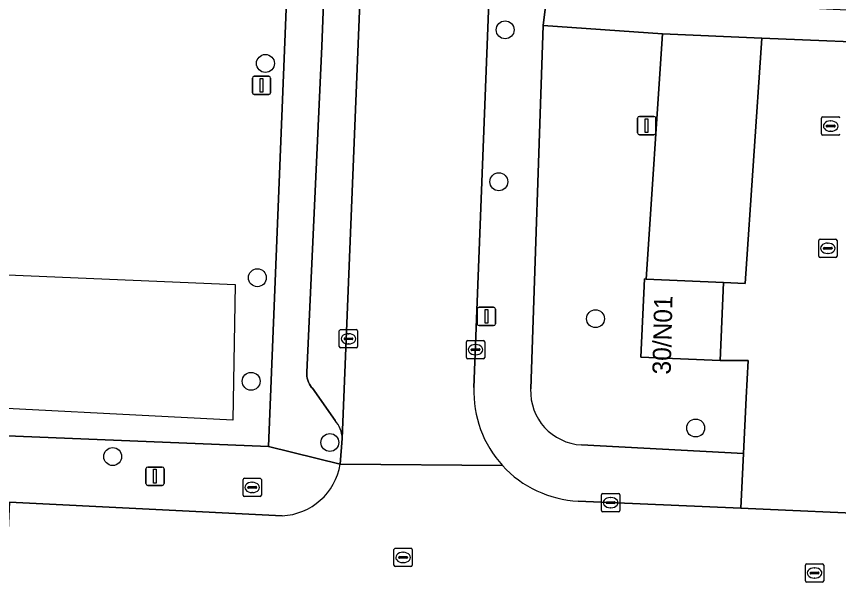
# Model space of a CAD drawing. Extents: x 161354 to 162026, y 386504 to 387460.
# Drawn here: x 161422.95 to 161467.8, y 386572.23 to 386603.95 of the extents above; entities that cross this region are included whole.
import ezdxf

# ---------------------------------------------------------------- set-up
doc = ezdxf.new("R2010")
doc.units = 0
for name, color, linetype in [('IMGEO_Boom', 7, 'Continuous'), ('IMGEO_Erf', 7, 'Continuous'), ('IMGEO_Groenvoorziening', 7, 'Continuous'), ('IMGEO_Kolk', 7, 'Continuous'), ('IMGEO_Lichtmast', 7, 'Continuous'), ('IMGEO_Pand', 7, 'Continuous'), ('IMGEO_Pand_nummerreeks', 7, 'Continuous'), ('IMGEO_Pand_vergunning_verleend', 7, 'Continuous'), ('IMGEO_Parkeervlak_open', 7, 'Continuous'), ('IMGEO_Rijbaan_lokaal_open', 7, 'Continuous'), ('IMGEO_Rioolput', 7, 'Continuous'), ('IMGEO_Voetpad_open', 7, 'Continuous')]:
    doc.layers.add(name, color=color, linetype=linetype)

msp = doc.modelspace()

# ---------------------------------------------------------------- linework, layer by layer
at = {"layer": 'IMGEO_Boom'}
for centre in [(161449.613, 386603.218), (161436.536, 386601.385), (161449.267, 386594.926), (161436.096, 386589.686), (161454.542, 386587.45), (161435.755, 386584.032), (161460.006, 386581.483), (161440.05, 386580.692), (161428.203, 386579.924)]:
    msp.add_circle(centre, 0.489, dxfattribs=at)
at = {"layer": 'IMGEO_Erf'}
msp.add_lwpolyline([(161420.217, 386581.152), (161436.711, 386580.469), (161438.937, 386635.916), (161439.242, 386644.412), (161439.468, 386649.379), (161441.486, 386649.282), (161445.22, 386736.534)], dxfattribs=at)
at = {"layer": 'IMGEO_Groenvoorziening'}
for points in [[(161458.197, 386602.999), (161451.688, 386603.457), (161451.005, 386583.617)], [(161453.783, 386580.56), (161462.617, 386580.096), (161462.764, 386583.132), (161462.863, 386585.172), (161461.34, 386585.162), (161457.019, 386585.355), (161457.209, 386589.618), (161457.314, 386589.613), (161458.197, 386602.999)]]:
    msp.add_lwpolyline(points, dxfattribs=at)
msp.add_arc((161453.937, 386583.491), 2.935, 177.5297, 266.9953, dxfattribs=at)
at = {"layer": 'IMGEO_Kolk'}
for p, q in [((161466.716, 386590.868), (161466.716, 386591.72)), ((161466.791, 386591.794), (161467.643, 386591.794)), ((161467.717, 386591.72), (161467.717, 386590.868)), ((161466.975, 386591.288), (161466.975, 386591.3)), ((161467.413, 386591.251), (161467.015, 386591.251)), ((161467.018, 386591.337), (161467.416, 386591.337)), ((161467.204, 386591.574), (161467.229, 386591.574)), ((161467.459, 386591.3), (161467.459, 386591.288)), ((161467.643, 386590.794), (161466.791, 386590.794)), ((161467.227, 386591.014), (161467.202, 386591.014)), ((161440.565, 386585.927), (161440.565, 386586.779)), ((161440.64, 386586.853), (161441.492, 386586.853)), ((161441.566, 386586.779), (161441.566, 386585.927)), ((161440.824, 386586.347), (161440.824, 386586.359)), ((161441.262, 386586.31), (161440.864, 386586.31)), ((161440.867, 386586.396), (161441.265, 386586.396)), ((161441.053, 386586.633), (161441.078, 386586.633)), ((161441.308, 386586.359), (161441.308, 386586.347)), ((161447.571, 386586.258), (161448.423, 386586.258)), ((161441.492, 386585.853), (161440.64, 386585.853)), ((161441.076, 386586.073), (161441.051, 386586.073)), ((161447.496, 386585.332), (161447.496, 386586.184)), ((161447.755, 386585.752), (161447.755, 386585.764)), ((161447.798, 386585.801), (161448.196, 386585.801)), ((161447.984, 386586.038), (161448.009, 386586.038)), ((161448.239, 386585.764), (161448.239, 386585.752)), ((161448.497, 386586.184), (161448.497, 386585.332)), ((161448.193, 386585.715), (161447.795, 386585.715)), ((161448.007, 386585.478), (161447.982, 386585.478)), ((161448.423, 386585.258), (161447.571, 386585.258)), ((161435.313, 386577.813), (161435.313, 386578.665)), ((161435.388, 386578.739), (161436.24, 386578.739)), ((161436.314, 386578.665), (161436.314, 386577.813)), ((161435.572, 386578.233), (161435.572, 386578.245)), ((161436.01, 386578.196), (161435.612, 386578.196)), ((161435.615, 386578.282), (161436.013, 386578.282)), ((161435.801, 386578.519), (161435.826, 386578.519)), ((161436.056, 386578.245), (161436.056, 386578.233)), ((161436.24, 386577.739), (161435.388, 386577.739)), ((161435.824, 386577.959), (161435.799, 386577.959)), ((161454.867, 386576.983), (161454.867, 386577.835)), ((161454.942, 386577.909), (161455.794, 386577.909)), ((161455.868, 386577.835), (161455.868, 386576.983)), ((161455.126, 386577.403), (161455.126, 386577.415)), ((161455.564, 386577.366), (161455.166, 386577.366)), ((161455.169, 386577.452), (161455.567, 386577.452)), ((161455.355, 386577.689), (161455.38, 386577.689)), ((161455.61, 386577.415), (161455.61, 386577.403)), ((161455.794, 386576.909), (161454.942, 386576.909)), ((161455.378, 386577.129), (161455.353, 386577.129))]:
    msp.add_line(p, q, dxfattribs=at)
for points in [[(161466.716, 386590.868), (161466.716, 386591.72)], [(161466.791, 386591.794), (161467.643, 386591.794)], [(161467.717, 386591.72), (161467.717, 386590.868)], [(161467.643, 386590.794), (161466.791, 386590.794)], [(161440.565, 386585.927), (161440.565, 386586.779)], [(161440.64, 386586.853), (161441.492, 386586.853)], [(161441.566, 386586.779), (161441.566, 386585.927)], [(161447.571, 386586.258), (161448.423, 386586.258)], [(161441.492, 386585.853), (161440.64, 386585.853)], [(161447.496, 386585.332), (161447.496, 386586.184)], [(161448.497, 386586.184), (161448.497, 386585.332)], [(161448.423, 386585.258), (161447.571, 386585.258)], [(161435.313, 386577.813), (161435.313, 386578.665)], [(161435.388, 386578.739), (161436.24, 386578.739)], [(161436.314, 386578.665), (161436.314, 386577.813)], [(161436.24, 386577.739), (161435.388, 386577.739)], [(161454.867, 386576.983), (161454.867, 386577.835)], [(161454.942, 386577.909), (161455.794, 386577.909)], [(161455.868, 386577.835), (161455.868, 386576.983)], [(161455.794, 386576.909), (161454.942, 386576.909)]]:
    msp.add_lwpolyline(points, dxfattribs=at)
for centre, radius, start, end in [((161466.793, 386591.718), 0.0765, 91.552, 178.448), ((161466.793, 386591.718), 0.0765, 91.552, 178.448), ((161467.641, 386591.718), 0.0765, 1.552, 88.448), ((161467.641, 386591.718), 0.0765, 1.552, 88.448), ((161467.015, 386591.297), 0.0403, 85.8775, 175.7526), ((161467.012, 386591.287), 0.0366, 178.938, 274.7102), ((161467.416, 386591.294), 0.043, 264.8664, 352.4533), ((161467.42, 386591.299), 0.0386, 1.7309, 96.639), ((161466.793, 386590.87), 0.0765, 181.552, 268.448), ((161466.793, 386590.87), 0.0765, 181.552, 268.448), ((161467.641, 386590.87), 0.0765, 271.552, 358.448), ((161467.641, 386590.87), 0.0765, 271.552, 358.448), ((161440.642, 386586.777), 0.0765, 91.552, 178.448), ((161440.642, 386586.777), 0.0765, 91.552, 178.448), ((161441.49, 386586.777), 0.0765, 1.552, 88.448), ((161441.49, 386586.777), 0.0765, 1.552, 88.448), ((161440.864, 386586.356), 0.0403, 85.8775, 175.7526), ((161440.861, 386586.346), 0.0366, 178.938, 274.7102), ((161441.265, 386586.353), 0.043, 264.8664, 352.4533), ((161441.269, 386586.358), 0.0386, 1.7309, 96.639), ((161447.573, 386586.182), 0.0765, 91.552, 178.448), ((161447.573, 386586.182), 0.0765, 91.552, 178.448), ((161448.421, 386586.182), 0.0765, 1.552, 88.448), ((161448.421, 386586.182), 0.0765, 1.552, 88.448), ((161440.642, 386585.929), 0.0765, 181.552, 268.448), ((161440.642, 386585.929), 0.0765, 181.552, 268.448), ((161441.49, 386585.929), 0.0765, 271.552, 358.448), ((161441.49, 386585.929), 0.0765, 271.552, 358.448), ((161447.795, 386585.761), 0.0403, 85.8775, 175.7526), ((161448.2, 386585.763), 0.0386, 1.7309, 96.639), ((161447.573, 386585.334), 0.0765, 181.552, 268.448), ((161447.573, 386585.334), 0.0765, 181.552, 268.448), ((161447.792, 386585.751), 0.0366, 178.938, 274.7102), ((161448.196, 386585.758), 0.043, 264.8664, 352.4533), ((161448.421, 386585.334), 0.0765, 271.552, 358.448), ((161448.421, 386585.334), 0.0765, 271.552, 358.448), ((161435.39, 386578.663), 0.0765, 91.552, 178.448), ((161435.39, 386578.663), 0.0765, 91.552, 178.448), ((161436.238, 386578.663), 0.0765, 1.552, 88.448), ((161436.238, 386578.663), 0.0765, 1.552, 88.448), ((161435.612, 386578.242), 0.0403, 85.8775, 175.7526), ((161435.609, 386578.232), 0.0366, 178.938, 274.7102), ((161436.013, 386578.239), 0.043, 264.8664, 352.4533), ((161436.017, 386578.244), 0.0386, 1.7309, 96.639), ((161435.39, 386577.815), 0.0765, 181.552, 268.448), ((161435.39, 386577.815), 0.0765, 181.552, 268.448), ((161436.238, 386577.815), 0.0765, 271.552, 358.448), ((161436.238, 386577.815), 0.0765, 271.552, 358.448), ((161454.944, 386577.833), 0.0765, 91.552, 178.448), ((161454.944, 386577.833), 0.0765, 91.552, 178.448), ((161455.792, 386577.833), 0.0765, 1.552, 88.448), ((161455.792, 386577.833), 0.0765, 1.552, 88.448), ((161455.166, 386577.412), 0.0403, 85.8775, 175.7526), ((161455.163, 386577.402), 0.0366, 178.938, 274.7102), ((161455.567, 386577.409), 0.043, 264.8664, 352.4533), ((161455.571, 386577.414), 0.0386, 1.7309, 96.639), ((161454.944, 386576.985), 0.0765, 181.552, 268.448), ((161454.944, 386576.985), 0.0765, 181.552, 268.448), ((161455.792, 386576.985), 0.0765, 271.552, 358.448), ((161455.792, 386576.985), 0.0765, 271.552, 358.448)]:
    msp.add_arc(centre, radius, start, end, dxfattribs=at)
for centre, major_axis, ratio, start_param, end_param in [((161467.203, 386591.294), (-0.387, 0.002), 0.722429, 4.712389, 7.853982), ((161467.228, 386591.294), (-0.39, 0.002), 0.717154, 1.570796, 4.712389), ((161441.052, 386586.353), (-0.387, 0.002), 0.722429, 4.712389, 7.853982), ((161441.077, 386586.353), (-0.39, 0.002), 0.717154, 1.570796, 4.712389), ((161447.983, 386585.758), (-0.387, 0.002), 0.722429, 4.712389, 7.853982), ((161448.008, 386585.758), (-0.39, 0.002), 0.717154, 1.570796, 4.712389), ((161435.8, 386578.239), (-0.387, 0.002), 0.722429, 4.712389, 7.853982), ((161435.825, 386578.239), (-0.39, 0.002), 0.717154, 1.570796, 4.712389), ((161455.354, 386577.409), (-0.387, 0.002), 0.722429, 4.712389, 7.853982), ((161455.379, 386577.409), (-0.39, 0.002), 0.717154, 1.570796, 4.712389)]:
    msp.add_ellipse(centre, major_axis=major_axis, ratio=ratio, start_param=start_param, end_param=end_param, dxfattribs=at)
at = {"layer": 'IMGEO_Lichtmast'}
for p, q in [((161435.828, 386599.788), (161435.828, 386600.588)), ((161435.828, 386600.588), (161435.828, 386599.788)), ((161435.928, 386600.688), (161436.718, 386600.688)), ((161436.718, 386600.688), (161435.928, 386600.688)), ((161436.818, 386600.588), (161436.818, 386599.788)), ((161436.818, 386599.788), (161436.818, 386600.588)), ((161436.718, 386599.688), (161435.928, 386599.688)), ((161435.928, 386599.688), (161436.718, 386599.688)), ((161456.834, 386597.592), (161456.834, 386598.392)), ((161456.834, 386598.392), (161456.834, 386597.592)), ((161456.934, 386598.492), (161457.724, 386598.492)), ((161457.724, 386598.492), (161456.934, 386598.492)), ((161457.824, 386598.392), (161457.824, 386597.592)), ((161457.824, 386597.592), (161457.824, 386598.392)), ((161457.724, 386597.492), (161456.934, 386597.492)), ((161456.934, 386597.492), (161457.724, 386597.492)), ((161448.195, 386588.074), (161448.985, 386588.074)), ((161448.985, 386588.074), (161448.195, 386588.074)), ((161448.095, 386587.174), (161448.095, 386587.974)), ((161448.095, 386587.974), (161448.095, 386587.174)), ((161449.085, 386587.974), (161449.085, 386587.174)), ((161449.085, 386587.174), (161449.085, 386587.974)), ((161448.985, 386587.074), (161448.195, 386587.074)), ((161448.195, 386587.074), (161448.985, 386587.074)), ((161430.013, 386578.453), (161430.013, 386579.253)), ((161430.013, 386579.253), (161430.013, 386578.453)), ((161430.113, 386579.353), (161430.903, 386579.353)), ((161430.903, 386579.353), (161430.113, 386579.353)), ((161431.003, 386579.253), (161431.003, 386578.453)), ((161431.003, 386578.453), (161431.003, 386579.253)), ((161430.903, 386578.353), (161430.113, 386578.353)), ((161430.113, 386578.353), (161430.903, 386578.353))]:
    msp.add_line(p, q, dxfattribs=at)
for points in [[(161436.248, 386600.563), (161436.398, 386600.563), (161436.398, 386599.813), (161436.248, 386599.813), (161436.248, 386600.563)], [(161457.254, 386598.367), (161457.404, 386598.367), (161457.404, 386597.617), (161457.254, 386597.617), (161457.254, 386598.367)], [(161448.515, 386587.949), (161448.665, 386587.949), (161448.665, 386587.199), (161448.515, 386587.199), (161448.515, 386587.949)], [(161430.433, 386579.228), (161430.583, 386579.228), (161430.583, 386578.478), (161430.433, 386578.478), (161430.433, 386579.228)]]:
    msp.add_lwpolyline(points, dxfattribs=at)
for centre, start, end in [((161435.928, 386600.588), 90, 180), ((161435.928, 386600.588), 90, 180), ((161436.718, 386600.588), 0, 90), ((161436.718, 386600.588), 360, 90), ((161435.928, 386599.788), 180, 270), ((161435.928, 386599.788), 180, 270), ((161436.718, 386599.788), 270, 0), ((161436.718, 386599.788), 270, 0), ((161456.934, 386598.392), 90, 180), ((161456.934, 386598.392), 90, 180), ((161457.724, 386598.392), 0, 90), ((161457.724, 386598.392), 360, 90), ((161456.934, 386597.592), 180, 270), ((161456.934, 386597.592), 180, 270), ((161457.724, 386597.592), 270, 0), ((161457.724, 386597.592), 270, 0), ((161448.195, 386587.974), 90, 180), ((161448.195, 386587.974), 90, 180), ((161448.985, 386587.974), 0, 90), ((161448.985, 386587.974), 360, 90), ((161448.195, 386587.174), 180, 270), ((161448.195, 386587.174), 180, 270), ((161448.985, 386587.174), 270, 0), ((161448.985, 386587.174), 270, 0), ((161430.113, 386579.253), 90, 180), ((161430.113, 386579.253), 90, 180), ((161430.903, 386579.253), 0, 90), ((161430.903, 386579.253), 360, 90), ((161430.113, 386578.453), 180, 270), ((161430.113, 386578.453), 180, 270), ((161430.903, 386578.453), 270, 0), ((161430.903, 386578.453), 270, 0)]:
    msp.add_arc(centre, 0.1, start, end, dxfattribs=at)
at = {"layer": 'IMGEO_Pand'}
msp.add_lwpolyline([(161457.209, 386589.618), (161457.019, 386585.355), (161461.34, 386585.162), (161461.53, 386589.425), (161457.314, 386589.613)], close=True, dxfattribs=at)
at = {"layer": 'IMGEO_Pand_vergunning_verleend'}
msp.add_lwpolyline([(161417.808, 386582.78), (161418.178, 386590.027), (161434.891, 386589.315), (161434.754, 386581.904)], close=True, dxfattribs=at)
at = {"layer": 'IMGEO_Parkeervlak_open'}
for points in [[(161440.728, 386580.914), (161442.775, 386631.664)], [(161440.573, 386628.239), (161440.169, 386617.127), (161439.605, 386602.315), (161438.792, 386584.526), (161438.792, 386584.415), (161438.801, 386584.304), (161438.82, 386584.195), (161438.849, 386584.088), (161438.888, 386583.983), (161438.936, 386583.883), (161438.992, 386583.787), (161439.057, 386583.697), (161439.095, 386583.651), (161440.338, 386581.897)]]:
    msp.add_lwpolyline(points, dxfattribs=at)
msp.add_lwpolyline([(161463.62, 386602.769), (161458.197, 386602.999), (161457.314, 386589.613), (161461.53, 386589.425), (161462.71, 386589.372)], close=True, dxfattribs=at)
msp.add_arc((161439.105, 386580.839), 1.624, 2.6444, 40.6365, dxfattribs=at)
at = {"layer": 'IMGEO_Rijbaan_lokaal_open'}
for points in [[(161449.677, 386629.063), (161449.81, 386631.874), (161442.786, 386632.138), (161442.775, 386631.664), (161440.728, 386580.914), (161440.612, 386579.503), (161449.473, 386579.428)], [(161447.912, 386583.7), (161449.677, 386629.063)], [(161471.607, 386602.43), (161463.62, 386602.769), (161462.71, 386589.372), (161461.53, 386589.425), (161461.34, 386585.162), (161462.863, 386585.172), (161462.764, 386583.132), (161462.617, 386580.096), (161462.472, 386577.103), (161470.606, 386576.745)], [(161449.473, 386579.428), (161440.612, 386579.503)], [(161437.448, 386576.695), (161422.578, 386577.43), (161422.296, 386571.701), (161427.114, 386571.524), (161432.125, 386571.303), (161435.713, 386571.139), (161436.471, 386571.13), (161480.42, 386569.303), (161480.459, 386569.293), (161481.407, 386569.291)], [(161494.106, 386563.966), (161494.216, 386567.185), (161494.164, 386567.428), (161494.05, 386567.79), (161493.905, 386568.14), (161493.896, 386568.159), (161493.46, 386569.194), (161492.934, 386570.186), (161492.321, 386571.127), (161491.627, 386572.009), (161491.379, 386572.288), (161490.356, 386573.271), (161489.25, 386574.158), (161488.069, 386574.943), (161487.91, 386575.037), (161486.247, 386575.67), (161484.636, 386576.127), (161470.606, 386576.745), (161462.472, 386577.103), (161453.59, 386577.494)]]:
    msp.add_lwpolyline(points, dxfattribs=at)
for centre, radius, start, end in [((161453.882, 386583.46), 5.975, 177.7015, 222.4434), ((161437.309, 386580.038), 3.346, 272.375, 350.8021), ((161453.881, 386583.462), 5.975, 222.4632, 267.2123)]:
    msp.add_arc(centre, radius, start, end, dxfattribs=at)
at = {"layer": 'IMGEO_Rioolput'}
for p, q in [((161466.874, 386597.539), (161466.874, 386598.391)), ((161466.949, 386598.465), (161467.801, 386598.465)), ((161467.133, 386597.959), (161467.133, 386597.971)), ((161467.571, 386597.922), (161467.173, 386597.922)), ((161467.176, 386598.008), (161467.574, 386598.008)), ((161467.362, 386598.245), (161467.387, 386598.245)), ((161467.617, 386597.971), (161467.617, 386597.959)), ((161467.801, 386597.465), (161466.949, 386597.465)), ((161467.385, 386597.685), (161467.36, 386597.685)), ((161443.546, 386573.991), (161443.546, 386574.843)), ((161443.621, 386574.917), (161444.473, 386574.917)), ((161444.034, 386574.697), (161444.059, 386574.697)), ((161444.547, 386574.843), (161444.547, 386573.991)), ((161443.805, 386574.411), (161443.805, 386574.423)), ((161444.243, 386574.374), (161443.845, 386574.374)), ((161443.848, 386574.46), (161444.246, 386574.46)), ((161444.057, 386574.137), (161444.032, 386574.137)), ((161444.289, 386574.423), (161444.289, 386574.411)), ((161444.473, 386573.917), (161443.621, 386573.917)), ((161465.991, 386573.142), (161465.991, 386573.994)), ((161466.066, 386574.068), (161466.918, 386574.068)), ((161466.479, 386573.848), (161466.504, 386573.848)), ((161466.992, 386573.994), (161466.992, 386573.142)), ((161466.25, 386573.562), (161466.25, 386573.574)), ((161466.688, 386573.525), (161466.29, 386573.525)), ((161466.293, 386573.611), (161466.691, 386573.611)), ((161466.502, 386573.288), (161466.477, 386573.288)), ((161466.734, 386573.574), (161466.734, 386573.562)), ((161466.918, 386573.068), (161466.066, 386573.068))]:
    msp.add_line(p, q, dxfattribs=at)
for points in [[(161466.874, 386597.539), (161466.874, 386598.391)], [(161466.949, 386598.465), (161467.801, 386598.465)], [(161467.801, 386597.465), (161466.949, 386597.465)], [(161443.546, 386573.991), (161443.546, 386574.843)], [(161443.621, 386574.917), (161444.473, 386574.917)], [(161444.547, 386574.843), (161444.547, 386573.991)], [(161444.473, 386573.917), (161443.621, 386573.917)], [(161465.991, 386573.142), (161465.991, 386573.994)], [(161466.066, 386574.068), (161466.918, 386574.068)], [(161466.992, 386573.994), (161466.992, 386573.142)], [(161466.918, 386573.068), (161466.066, 386573.068)]]:
    msp.add_lwpolyline(points, dxfattribs=at)
for centre, radius, start, end in [((161466.951, 386598.389), 0.0765, 91.552, 178.448), ((161466.951, 386598.389), 0.0765, 91.552, 178.448), ((161467.799, 386598.389), 0.0765, 1.552, 88.448), ((161467.799, 386598.389), 0.0765, 1.552, 88.448), ((161467.173, 386597.968), 0.0403, 85.8775, 175.7526), ((161467.17, 386597.958), 0.0366, 178.938, 274.7102), ((161467.574, 386597.965), 0.043, 264.8664, 352.4533), ((161467.578, 386597.97), 0.0386, 1.7309, 96.639), ((161466.951, 386597.541), 0.0765, 181.552, 268.448), ((161466.951, 386597.541), 0.0765, 181.552, 268.448), ((161467.799, 386597.541), 0.0765, 271.552, 358.448), ((161467.799, 386597.541), 0.0765, 271.552, 358.448), ((161443.623, 386574.841), 0.0765, 91.552, 178.448), ((161443.623, 386574.841), 0.0765, 91.552, 178.448), ((161444.471, 386574.841), 0.0765, 1.552, 88.448), ((161444.471, 386574.841), 0.0765, 1.552, 88.448), ((161443.845, 386574.42), 0.0403, 85.8775, 175.7526), ((161443.842, 386574.41), 0.0366, 178.938, 274.7102), ((161444.246, 386574.417), 0.043, 264.8664, 352.4533), ((161444.25, 386574.422), 0.0386, 1.7309, 96.639), ((161443.623, 386573.993), 0.0765, 181.552, 268.448), ((161443.623, 386573.993), 0.0765, 181.552, 268.448), ((161444.471, 386573.993), 0.0765, 271.552, 358.448), ((161444.471, 386573.993), 0.0765, 271.552, 358.448), ((161466.068, 386573.992), 0.0765, 91.552, 178.448), ((161466.068, 386573.992), 0.0765, 91.552, 178.448), ((161466.916, 386573.992), 0.0765, 1.552, 88.448), ((161466.916, 386573.992), 0.0765, 1.552, 88.448), ((161466.29, 386573.571), 0.0403, 85.8775, 175.7526), ((161466.287, 386573.561), 0.0366, 178.938, 274.7102), ((161466.691, 386573.568), 0.043, 264.8664, 352.4533), ((161466.695, 386573.573), 0.0386, 1.7309, 96.639), ((161466.068, 386573.144), 0.0765, 181.552, 268.448), ((161466.068, 386573.144), 0.0765, 181.552, 268.448), ((161466.916, 386573.144), 0.0765, 271.552, 358.448), ((161466.916, 386573.144), 0.0765, 271.552, 358.448)]:
    msp.add_arc(centre, radius, start, end, dxfattribs=at)
for centre, major_axis, ratio, start_param, end_param in [((161467.361, 386597.965), (-0.387, 0.002), 0.722429, 4.712389, 7.853982), ((161467.386, 386597.965), (-0.39, 0.002), 0.717154, 1.570796, 4.712389), ((161444.033, 386574.417), (-0.387, 0.002), 0.722429, 4.712389, 7.853982), ((161444.058, 386574.417), (-0.39, 0.002), 0.717154, 1.570796, 4.712389), ((161466.478, 386573.568), (-0.387, 0.002), 0.722429, 4.712389, 7.853982), ((161466.503, 386573.568), (-0.39, 0.002), 0.717154, 1.570796, 4.712389)]:
    msp.add_ellipse(centre, major_axis=major_axis, ratio=ratio, start_param=start_param, end_param=end_param, dxfattribs=at)
at = {"layer": 'IMGEO_Voetpad_open'}
for points in [[(161450.51, 386646.622), (161449.943, 386634.664), (161449.81, 386631.874), (161449.677, 386629.063), (161447.912, 386583.7)], [(161451.005, 386583.617), (161451.688, 386603.457), (161451.893, 386605.086), (161453.182, 386636.23)], [(161442.775, 386631.664), (161442.786, 386632.138), (161442.881, 386634.986), (161442.98, 386635.811), (161438.937, 386635.916), (161436.711, 386580.469), (161440.612, 386579.503), (161440.728, 386580.914)], [(161439.605, 386602.315), (161440.169, 386617.127), (161440.573, 386628.239)], [(161440.338, 386581.897), (161439.095, 386583.651), (161439.057, 386583.697), (161438.992, 386583.787), (161438.936, 386583.883), (161438.888, 386583.983), (161438.849, 386584.088), (161438.82, 386584.195), (161438.801, 386584.304), (161438.792, 386584.415), (161438.792, 386584.526), (161439.605, 386602.315)], [(161440.612, 386579.503), (161436.711, 386580.469), (161420.217, 386581.152), (161418.55, 386540.528), (161418.541, 386540.389), (161418.612, 386534.37), (161418.897, 386534.449), (161419.174, 386534.553), (161419.44, 386534.682), (161419.694, 386534.833), (161419.934, 386535.007), (161420.156, 386535.202), (161420.361, 386535.415), (161420.546, 386535.647), (161420.709, 386535.893), (161420.849, 386536.153), (161420.966, 386536.425), (161421.058, 386536.706), (161421.125, 386536.994), (161421.165, 386537.287), (161421.177, 386537.467), (161422.296, 386571.701), (161422.578, 386577.43), (161437.448, 386576.695)], [(161453.59, 386577.494), (161462.472, 386577.103), (161462.617, 386580.096), (161453.783, 386580.56)]]:
    msp.add_lwpolyline(points, dxfattribs=at)
msp.add_lwpolyline([(161458.156, 386604.78), (161451.893, 386605.086), (161451.688, 386603.457), (161458.197, 386602.999), (161463.62, 386602.769), (161471.607, 386602.43), (161471.609, 386602.595), (161471.796, 386607.592), (161471.832, 386608.541), (161471.937, 386609.792), (161470.345, 386609.864), (161470.12, 386604.195)], close=True, dxfattribs=at)
for centre, radius, start, end in [((161453.882, 386583.46), 5.975, 177.7015, 222.4434), ((161453.937, 386583.491), 2.935, 177.5297, 266.9953), ((161439.105, 386580.839), 1.624, 2.6444, 40.6365), ((161437.309, 386580.038), 3.346, 272.375, 350.8021), ((161453.881, 386583.462), 5.975, 222.4632, 267.2123)]:
    msp.add_arc(centre, radius, start, end, dxfattribs=at)

# ---------------------------------------------------------------- texts
at = {"layer": 'IMGEO_Pand_nummerreeks'}
msp.add_text('30/N01', height=1, rotation=88.6361, dxfattribs=at).set_placement((161458.643, 386584.396))

doc.saveas('drawing.dxf')
